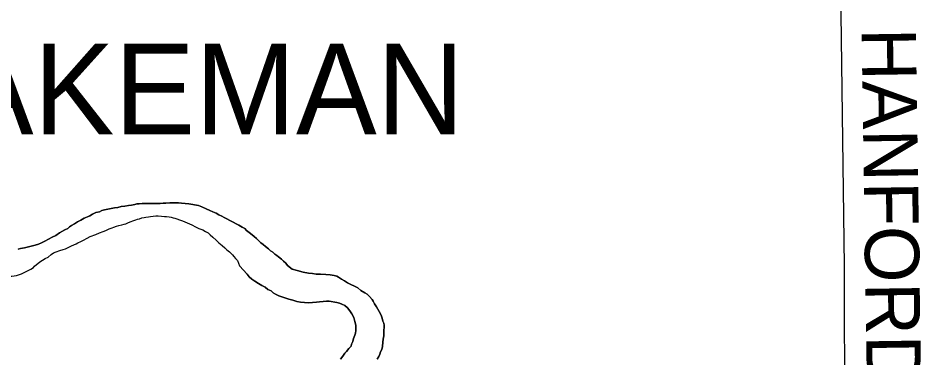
# Model space of a CAD drawing. Extents: x 0 to 34, y 0 to 22.
# Drawn here: x 5.531 to 6.476, y 17.8 to 18.155 of the extents above; entities that cross this region are included whole.
import ezdxf

# ---------------------------------------------------------------- set-up
doc = ezdxf.new("R2010")
doc.units = 0
for name, color, linetype in [('GM_X_Corporation_Text', 7, 'Continuous'), ('GM_X_Major_River', 7, 'Continuous'), ('GM_X_Township_Road', 7, 'Continuous'), ('GM_X_Township_Road_Text', 7, 'Continuous')]:
    doc.layers.add(name, color=color, linetype=linetype)

msp = doc.modelspace()

# ---------------------------------------------------------------- linework, layer by layer
at = {"layer": 'GM_X_Major_River'}
for points in [[(5.81317, 17.8963), (5.81141, 17.89883), (5.80913, 17.90111), (5.80685, 17.90302), (5.80382, 17.9053), (5.80192, 17.90682), (5.80002, 17.90835), (5.79774, 17.91025), (5.79546, 17.91177), (5.79318, 17.91368), (5.79015, 17.91634), (5.78787, 17.91824), (5.78521, 17.92015), (5.78294, 17.92243), (5.78066, 17.92472), (5.77838, 17.92662), (5.7761, 17.92852), (5.77307, 17.93081), (5.77041, 17.93309), (5.76851, 17.93499), (5.76585, 17.93652), (5.76244, 17.93842), (5.7594, 17.93995), (5.75636, 17.94185), (5.75294, 17.94337), (5.7499, 17.94528), (5.74687, 17.94642), (5.74459, 17.94795), (5.74155, 17.94947), (5.73851, 17.95099), (5.73509, 17.95252), (5.73206, 17.95404), (5.72826, 17.95557), (5.7237, 17.95785), (5.72028, 17.959), (5.71002, 17.96091), (5.70622, 17.96129), (5.70243, 17.96167), (5.69939, 17.96205), (5.69635, 17.96206), (5.69331, 17.96206), (5.69027, 17.96206), (5.68609, 17.96169), (5.68305, 17.96169), (5.68001, 17.96131), (5.67735, 17.96131), (5.67431, 17.96132), (5.67127, 17.96132), (5.66785, 17.96132), (5.66481, 17.96132), (5.66139, 17.96133), (5.65797, 17.96095), (5.65569, 17.96095), (5.65341, 17.96019), (5.64999, 17.95943), (5.64695, 17.95906), (5.64315, 17.9583), (5.63935, 17.95792), (5.63593, 17.95716), (5.63213, 17.95679), (5.62871, 17.95603), (5.62529, 17.95527), (5.62187, 17.95451), (5.61921, 17.95375), (5.61654, 17.95262), (5.61274, 17.95186), (5.60932, 17.94996), (5.60666, 17.94844), (5.604, 17.9473), (5.60058, 17.94578), (5.59716, 17.94388), (5.59373, 17.94198), (5.59031, 17.94009), (5.58727, 17.93819), (5.58537, 17.93667), (5.58347, 17.93515), (5.58043, 17.93363), (5.57472, 17.93059), (5.57092, 17.92793), (5.56712, 17.92603), (5.56332, 17.92376), (5.55951, 17.92186), (5.5561, 17.91996), (5.55267, 17.91882), (5.54925, 17.91768), (5.53823, 17.91503), (5.53405, 17.91427), (5.53139, 17.91351)], [(5.53139, 17.91351), (5.53405, 17.91427), (5.53823, 17.91503), (5.54925, 17.91768), (5.55267, 17.91882), (5.5561, 17.91996), (5.55951, 17.92186), (5.56332, 17.92376), (5.56712, 17.92603), (5.57092, 17.92793), (5.57472, 17.93059), (5.58043, 17.93363), (5.58347, 17.93515), (5.58537, 17.93667), (5.58727, 17.93819), (5.59031, 17.94009), (5.59373, 17.94198), (5.59716, 17.94388), (5.60058, 17.94578), (5.604, 17.9473), (5.60666, 17.94844), (5.60932, 17.94996), (5.61274, 17.95186), (5.61654, 17.95262), (5.61921, 17.95375), (5.62187, 17.95451), (5.62529, 17.95527), (5.62871, 17.95603), (5.63213, 17.95679), (5.63593, 17.95716), (5.63935, 17.95792), (5.64315, 17.9583), (5.64695, 17.95906), (5.64999, 17.95943), (5.65341, 17.96019), (5.65569, 17.96095), (5.65797, 17.96095), (5.66139, 17.96133), (5.66481, 17.96132), (5.66785, 17.96132), (5.67127, 17.96132), (5.67431, 17.96132), (5.67735, 17.96131), (5.68001, 17.96131), (5.68305, 17.96169), (5.68609, 17.96169), (5.69027, 17.96206), (5.69331, 17.96206), (5.69635, 17.96206), (5.69939, 17.96205), (5.70243, 17.96167), (5.70622, 17.96129), (5.71002, 17.96091), (5.72028, 17.959), (5.7237, 17.95785), (5.72826, 17.95557), (5.73206, 17.95404), (5.73509, 17.95252), (5.73851, 17.95099), (5.74155, 17.94947), (5.74459, 17.94795), (5.74687, 17.94642), (5.7499, 17.94528), (5.75294, 17.94337), (5.75636, 17.94185), (5.7594, 17.93995), (5.76244, 17.93842), (5.76585, 17.93652), (5.76851, 17.93499), (5.77041, 17.93309), (5.77307, 17.93081), (5.7761, 17.92852), (5.77838, 17.92662), (5.78066, 17.92472), (5.78294, 17.92243), (5.78521, 17.92015), (5.78787, 17.91824), (5.79015, 17.91634), (5.79318, 17.91368), (5.79546, 17.91177), (5.79774, 17.91025), (5.80002, 17.90835), (5.80192, 17.90682), (5.80382, 17.9053), (5.80685, 17.90302), (5.80913, 17.90111), (5.81141, 17.89883), (5.81317, 17.8963)], [(5.54742, 17.89437), (5.54847, 17.89562), (5.55417, 17.90018), (5.55988, 17.9036), (5.56292, 17.90512), (5.56596, 17.90778), (5.56862, 17.90968), (5.57128, 17.91082), (5.57508, 17.91196), (5.5785, 17.91309), (5.58117, 17.91385), (5.58725, 17.91689), (5.58991, 17.91803), (5.59219, 17.91917), (5.59409, 17.91993), (5.59713, 17.92144), (5.59979, 17.92296), (5.60359, 17.92486), (5.60702, 17.92676), (5.61272, 17.92866), (5.61652, 17.93056), (5.62032, 17.93208), (5.62336, 17.93283), (5.62679, 17.93473), (5.62982, 17.93587), (5.63173, 17.93663), (5.63439, 17.93739), (5.63667, 17.93815), (5.64009, 17.93891), (5.64237, 17.93966), (5.64427, 17.94004), (5.64693, 17.94118), (5.64959, 17.94232), (5.65149, 17.94308), (5.65453, 17.94422), (5.65643, 17.94498), (5.65833, 17.94535), (5.66099, 17.94611), (5.66327, 17.94649), (5.66517, 17.94687), (5.66783, 17.94725), (5.67011, 17.94763), (5.67277, 17.94801), (5.67543, 17.94838), (5.67809, 17.94838), (5.68151, 17.948), (5.68455, 17.94762), (5.68683, 17.94761), (5.68949, 17.94723), (5.69139, 17.94685), (5.69367, 17.94609), (5.69557, 17.9457), (5.69747, 17.94532), (5.70013, 17.94418), (5.70354, 17.94304), (5.71304, 17.93884), (5.71684, 17.93694), (5.72063, 17.93503), (5.72481, 17.93351), (5.72747, 17.93199), (5.73013, 17.93046), (5.73241, 17.92856), (5.73506, 17.9259), (5.73848, 17.92285), (5.74152, 17.92019), (5.74493, 17.91714), (5.74759, 17.91485), (5.74987, 17.91295), (5.75253, 17.91067), (5.75556, 17.90762), (5.75708, 17.90572), (5.75898, 17.90382), (5.76087, 17.90153), (5.76315, 17.89607)], [(5.54742, 17.89437), (5.54847, 17.89562), (5.55417, 17.90018), (5.55988, 17.9036), (5.56292, 17.90512), (5.56596, 17.90778), (5.56862, 17.90968), (5.57128, 17.91082), (5.57508, 17.91196), (5.5785, 17.91309), (5.58117, 17.91385), (5.58725, 17.91689), (5.58991, 17.91803), (5.59219, 17.91917), (5.59409, 17.91993), (5.59713, 17.92144), (5.59979, 17.92296), (5.60359, 17.92486), (5.60702, 17.92676), (5.61272, 17.92866), (5.61652, 17.93056), (5.62032, 17.93208), (5.62336, 17.93283), (5.62679, 17.93473), (5.62982, 17.93587), (5.63173, 17.93663), (5.63439, 17.93739), (5.63667, 17.93815), (5.64009, 17.93891), (5.64237, 17.93966), (5.64427, 17.94004), (5.64693, 17.94118), (5.64959, 17.94232), (5.65149, 17.94308), (5.65453, 17.94422), (5.65643, 17.94498), (5.65833, 17.94535), (5.66099, 17.94611), (5.66327, 17.94649), (5.66517, 17.94687), (5.66783, 17.94725), (5.67011, 17.94763), (5.67277, 17.94801), (5.67543, 17.94838), (5.67809, 17.94838), (5.68151, 17.948), (5.68455, 17.94762), (5.68683, 17.94761), (5.68949, 17.94723), (5.69139, 17.94685), (5.69367, 17.94609), (5.69557, 17.9457), (5.69747, 17.94532), (5.70013, 17.94418), (5.70354, 17.94304), (5.71304, 17.93884), (5.71684, 17.93694), (5.72063, 17.93503), (5.72481, 17.93351), (5.72747, 17.93199), (5.73013, 17.93046), (5.73241, 17.92856), (5.73506, 17.9259), (5.73848, 17.92285), (5.74152, 17.92019), (5.74493, 17.91714), (5.74759, 17.91485), (5.74987, 17.91295), (5.75253, 17.91067), (5.75556, 17.90762), (5.75708, 17.90572), (5.75898, 17.90382), (5.76087, 17.90153), (5.76315, 17.89607)], [(5.38356, 17.895), (5.3979, 17.88602), (5.40292, 17.88435), (5.40876, 17.88268), (5.41544, 17.88184), (5.42964, 17.88184), (5.44134, 17.88351), (5.44719, 17.88518), (5.4522, 17.88602), (5.45888, 17.88518), (5.46473, 17.88518), (5.46974, 17.88434), (5.47559, 17.88351), (5.4806, 17.88351), (5.48728, 17.88267), (5.4948, 17.88267), (5.50148, 17.88351), (5.50816, 17.88351), (5.51819, 17.88518), (5.52487, 17.88518), (5.52988, 17.88601), (5.53489, 17.88768), (5.54492, 17.89269), (5.54742, 17.89437)], [(5.76315, 17.89607), (5.77087, 17.88721), (5.77312, 17.88452), (5.77575, 17.88221), (5.77915, 17.87988), (5.78292, 17.87756), (5.78632, 17.87562), (5.78972, 17.87368), (5.79273, 17.87136), (5.79613, 17.8698), (5.79839, 17.86787), (5.80065, 17.86633), (5.80405, 17.86476), (5.80935, 17.8628), (5.81465, 17.86122), (5.81882, 17.86003), (5.82299, 17.85884), (5.82678, 17.85803), (5.83096, 17.8576), (5.83514, 17.85755), (5.83932, 17.85788), (5.84351, 17.85821), (5.84655, 17.85856), (5.85036, 17.85889), (5.85416, 17.85923), (5.85683, 17.85919), (5.86479, 17.85758), (5.86745, 17.85717), (5.87009, 17.856), (5.87311, 17.85444), (5.87613, 17.85212), (5.87837, 17.84906), (5.88062, 17.84599), (5.88247, 17.84217), (5.88356, 17.83797), (5.88466, 17.83416), (5.88462, 17.83112), (5.88459, 17.82846), (5.88418, 17.8258), (5.88377, 17.82352), (5.88221, 17.82012), (5.88141, 17.81709), (5.88023, 17.81406), (5.87983, 17.81217), (5.87752, 17.80953), (5.87482, 17.80652), (5.87328, 17.80464), (5.87096, 17.80163), (5.86864, 17.79862)], [(5.86864, 17.79862), (5.87096, 17.80163), (5.87328, 17.80464), (5.87482, 17.80652), (5.87752, 17.80953), (5.87983, 17.81217), (5.88023, 17.81406), (5.88141, 17.81709), (5.88221, 17.82012), (5.88377, 17.82352), (5.88418, 17.8258), (5.88459, 17.82846), (5.88462, 17.83112), (5.88466, 17.83416), (5.88356, 17.83797), (5.88247, 17.84217), (5.88062, 17.84599), (5.87837, 17.84906), (5.87613, 17.85212), (5.87311, 17.85444), (5.87009, 17.856), (5.86745, 17.85717), (5.86479, 17.85758), (5.85683, 17.85919), (5.85416, 17.85923), (5.85036, 17.85889), (5.84655, 17.85856), (5.84351, 17.85821), (5.83932, 17.85788), (5.83514, 17.85755), (5.83096, 17.8576), (5.82678, 17.85803), (5.82299, 17.85884), (5.81882, 17.86003), (5.81465, 17.86122), (5.80935, 17.8628), (5.80405, 17.86476), (5.80065, 17.86633), (5.79839, 17.86787), (5.79613, 17.8698), (5.79273, 17.87136), (5.78972, 17.87368), (5.78632, 17.87562), (5.78292, 17.87756), (5.77915, 17.87988), (5.77575, 17.88221), (5.77312, 17.88452), (5.77087, 17.88721), (5.76315, 17.89607)], [(5.90704, 17.79854), (5.90859, 17.80118), (5.90976, 17.80383), (5.91055, 17.8061), (5.91172, 17.80875), (5.91252, 17.81178), (5.91295, 17.81634), (5.91337, 17.81937), (5.91379, 17.82279), (5.91382, 17.82583), (5.91386, 17.82887), (5.91428, 17.83153), (5.91431, 17.83419), (5.91395, 17.83609), (5.91284, 17.83838), (5.91211, 17.84144), (5.91101, 17.84449), (5.90915, 17.84831), (5.90766, 17.85061), (5.90617, 17.85329), (5.90431, 17.85635), (5.90282, 17.85903), (5.9017, 17.86094), (5.89908, 17.86402), (5.89645, 17.86633), (5.89418, 17.86788), (5.89003, 17.87021), (5.88664, 17.87291), (5.88324, 17.87485), (5.87946, 17.87641), (5.87606, 17.87836), (5.87267, 17.8803), (5.86965, 17.88223), (5.86663, 17.88417), (5.86474, 17.88533), (5.86209, 17.88612), (5.85792, 17.88655), (5.85336, 17.88699), (5.84766, 17.88743), (5.8431, 17.88749), (5.83931, 17.88791), (5.83513, 17.88834), (5.82944, 17.88955), (5.82338, 17.89114), (5.81807, 17.89273), (5.81317, 17.8963)], [(5.81317, 17.8963), (5.81807, 17.89273), (5.82338, 17.89114), (5.82944, 17.88955), (5.83513, 17.88834), (5.83931, 17.88791), (5.8431, 17.88749), (5.84766, 17.88743), (5.85336, 17.88699), (5.85792, 17.88655), (5.86209, 17.88612), (5.86474, 17.88533), (5.86663, 17.88417), (5.86965, 17.88223), (5.87267, 17.8803), (5.87606, 17.87836), (5.87946, 17.87641), (5.88324, 17.87485), (5.88664, 17.87291), (5.89003, 17.87021), (5.89418, 17.86788), (5.89645, 17.86633), (5.89908, 17.86402), (5.9017, 17.86094), (5.90282, 17.85903), (5.90431, 17.85635), (5.90617, 17.85329), (5.90766, 17.85061), (5.90915, 17.84831), (5.91101, 17.84449), (5.91211, 17.84144), (5.91284, 17.83838), (5.91395, 17.83609), (5.91431, 17.83419), (5.91428, 17.83153), (5.91386, 17.82887), (5.91382, 17.82583), (5.91379, 17.82279), (5.91337, 17.81937), (5.91295, 17.81634), (5.91252, 17.81178), (5.91172, 17.80875), (5.91055, 17.8061), (5.90976, 17.80383), (5.90859, 17.80118), (5.90704, 17.79854)]]:
    msp.add_lwpolyline(points, dxfattribs=at)
at = {"layer": 'GM_X_Township_Road'}
msp.add_lwpolyline([(6.38001, 17.13374), (6.37968, 17.16034), (6.38233, 17.17439), (6.38575, 17.19072), (6.39864, 17.21502), (6.40243, 17.22603), (6.40508, 17.24047), (6.40203, 17.29668), (6.40011, 17.3601), (6.40275, 17.38821), (6.40503, 17.39732), (6.41148, 17.41137), (6.42057, 17.43415), (6.42208, 17.44479), (6.41981, 17.45732), (6.40347, 17.50898), (6.40044, 17.52228), (6.39853, 17.55039), (6.39619, 17.73307), (6.39576, 17.896), (6.39102, 18.23889)], dxfattribs=at)

# ---------------------------------------------------------------- texts
at = {"layer": 'GM_X_Corporation_Text'}
msp.add_text('WAKEMAN', height=0.094697, rotation=0.00001, dxfattribs=at).set_placement((5.3437, 18.03346))
at = {"layer": 'GM_X_Township_Road_Text'}
msp.add_text('HANFORD', height=0.056818, rotation=270.84975, dxfattribs=at).set_placement((6.41354, 18.14413))

doc.saveas('drawing.dxf')
